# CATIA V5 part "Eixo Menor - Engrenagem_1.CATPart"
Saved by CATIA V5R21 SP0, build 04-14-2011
Part number: Eixo Menor - Engrenagem_1
Definition: Eixo Menor - Engrenagem_1
Nomenclature: Eixo Menor - Engrenagem
Source: Unknown
Bounding box of the stored display mesh (mm): x -0.45 to 0.45, y 0 to 3.8, z -0.45 to 0.45
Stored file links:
  C:\Users\beatr\OneDrive\Documents\UNB\2026_1\Pi1\Componentes eletronicos\Eixo Menor - Engrenagem_1.CATPart
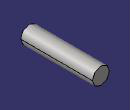
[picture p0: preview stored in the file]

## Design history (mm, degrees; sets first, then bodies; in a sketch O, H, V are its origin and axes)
Body1 "Sólido1" (main body)
  Solid1: solid without history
